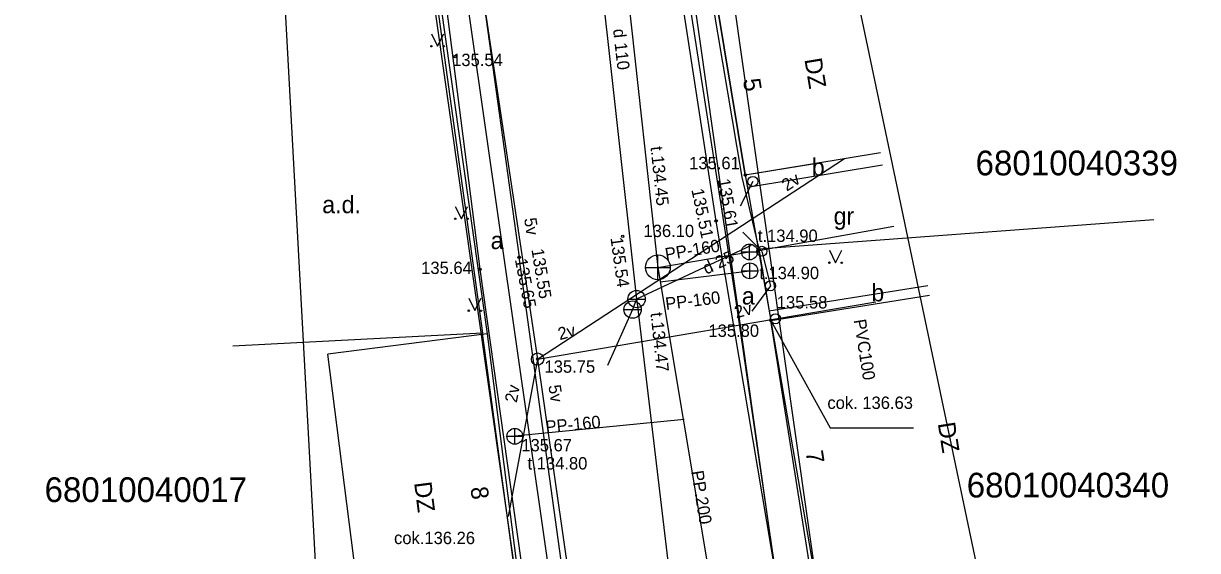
# Model space of a CAD drawing. Extents: x 728710 to 728960, y 272811 to 273475.
# Drawn here: x 728763.33 to 728810.77, y 273320.09 to 273341.41 of the extents above; entities that cross this region are included whole.
import ezdxf

# ---------------------------------------------------------------- set-up
doc = ezdxf.new("R2010")
doc.units = 0
for name, color, linetype in [('Level 15', 7, 'Continuous'), ('Level 17', 7, 'Continuous'), ('Level 21', 7, 'Continuous'), ('Level 23', 7, 'Continuous'), ('Level 25', 7, 'Continuous'), ('Level 28', 7, 'Continuous'), ('Level 29', 7, 'Continuous'), ('Level 3', 7, 'Continuous'), ('Level 35', 7, 'Continuous'), ('Level 39', 7, 'Continuous'), ('Level 4', 7, 'Continuous'), ('Level 41', 7, 'Continuous'), ('Level 42', 7, 'Continuous'), ('Level 43', 7, 'Continuous'), ('Level 48', 7, 'Continuous'), ('Level 50', 7, 'Continuous'), ('Level 53', 7, 'Continuous'), ('Level 55', 7, 'Continuous'), ('Level 56', 7, 'Continuous'), ('Level 57', 7, 'Continuous'), ('Level 58', 7, 'Continuous'), ('Level 59', 7, 'Continuous'), ('Level 60', 7, 'Continuous'), ('Level 62', 7, 'Continuous'), ('Level 9', 7, 'Continuous'), ('RAMI_UZMR_####_####_#', 7, 'Continuous'), ('ROBZ_ELEM_####_####_#', 7, 'Continuous'), ('ROBZ_KADS_####_TKST_#', 7, 'Continuous'), ('ROBZ_UZMR_####_####_#', 7, 'Continuous'), ('TERT_KOKR_####_####_#', 7, 'Continuous'), ('TERT_KONT_####_####_#', 7, 'Continuous')]:
    doc.layers.add(name, color=color, linetype=linetype)

msp = doc.modelspace()

# ---------------------------------------------------------------- linework, layer by layer
at = {"layer": 'Level 15'}
msp.add_circle((728784.106, 273327.834), 0.25, dxfattribs=at)
at = {"layer": 'Level 17'}
msp.add_line((728792.736, 273332.422), (728788.106, 273330.262), dxfattribs=at)
for points in [[(728784.072, 273366.484), (728788.106, 273330.262)], [(728788.106, 273330.262), (728787.947, 273329.838), (728786.937, 273327.58)], [(728788.106, 273330.262), (728788.125, 273330.089), (728790.41, 273310.945)]]:
    msp.add_lwpolyline(points, dxfattribs=at)
at = {"layer": 'Level 21'}
for p, q in [((728780.859, 273349.374), (728784.106, 273327.834)), ((728784.106, 273327.834), (728796.502, 273335.944)), ((728784.106, 273327.834), (728797.773, 273330.151)), ((728784.106, 273327.834), (728782.92, 273321.472)), ((728784.106, 273327.834), (728789.056, 273293.323))]:
    msp.add_line(p, q, dxfattribs=at)
at = {"layer": 'Level 23'}
for p, q in [((728785.477, 273363.156), (728788.967, 273331.545)), ((728788.967, 273331.545), (728792.668, 273332.168)), ((728788.967, 273331.545), (728795, 273295.478)), ((728789.065, 273330.958), (728792.684, 273331.404)), ((728790.024, 273325.392), (728783.185, 273324.713))]:
    msp.add_line(p, q, dxfattribs=at)
at = {"layer": 'Level 25'}
msp.add_lwpolyline([(728785.99, 273372.886), (728785.832, 273372.861), (728785.75, 273372.839), (728785.702, 273372.779), (728785.739, 273372.573), (728785.909, 273371.858), (728786.217, 273369.716), (728787.857, 273356.655), (728789.858, 273344.74), (728792.105, 273330.272), (728794.886, 273311.104), (728800.258, 273275.541), (728800.246, 273275.285), (728800.191, 273275.06), (728800.047, 273274.884), (728788.271, 273273.105), (728788.2, 273273.054), (728788.171, 273272.955), (728788.447, 273271.634)], dxfattribs=at)
at = {"layer": 'Level 28'}
msp.add_lwpolyline([(728793.169, 273332.187), (728793.514, 273330.801)], dxfattribs=at)
at = {"layer": 'Level 29'}
for p, q in [((728792.668, 273331.848), (728792.668, 273332.488)), ((728788.967, 273331.045), (728788.967, 273332.045)), ((728792.348, 273332.168), (728792.988, 273332.168)), ((728788.467, 273331.545), (728789.467, 273331.545)), ((728792.364, 273331.404), (728793.004, 273331.404)), ((728792.684, 273331.084), (728792.684, 273331.724)), ((728782.865, 273324.713), (728783.505, 273324.713)), ((728783.185, 273324.393), (728783.185, 273325.033))]:
    msp.add_line(p, q, dxfattribs=at)
for centre, radius in [((728792.668, 273332.168), 0.32), ((728788.967, 273331.545), 0.5), ((728792.684, 273331.404), 0.32), ((728783.185, 273324.713), 0.32)]:
    msp.add_circle(centre, radius, dxfattribs=at)
at = {"layer": 'Level 3'}
for p, q in [((728792.498, 273335.28), (728791.362, 273342.132)), ((728792.498, 273335.28), (728797.96, 273336.186)), ((728793.525, 273329.397), (728799.941, 273330.419)), ((728795.323, 273318.108), (728793.525, 273329.397)), ((728782.064, 273328.858), (728775.625, 273328.034)), ((728782.064, 273328.858), (728783.658, 273316.396)), ((728777.219, 273315.572), (728775.625, 273328.034))]:
    msp.add_line(p, q, dxfattribs=at)
msp.add_lwpolyline([(728794.003, 273342.57), (728791.362, 273342.132), (728792.498, 273335.28), (728795.229, 273335.733)], dxfattribs=at)
at = {"layer": 'Level 35'}
msp.add_lwpolyline([(728779.067, 273350.123), (728782.064, 273328.858)], dxfattribs=at)
at = {"layer": 'Level 39'}
for p, q in [((728787.755, 273330.262), (728788.458, 273330.262)), ((728788.105, 273330.262), (728788.105, 273330.263)), ((728787.595, 273329.838), (728788.298, 273329.838)), ((728787.946, 273329.838), (728787.946, 273329.839))]:
    msp.add_line(p, q, dxfattribs=at)
for centre in [(728788.106, 273330.262), (728787.947, 273329.838)]:
    msp.add_circle(centre, 0.351, dxfattribs=at)
at = {"layer": 'Level 4'}
for p, q in [((728792.584, 273334.788), (728798.042, 273335.692)), ((728792.498, 273335.28), (728793.525, 273329.397)), ((728794.133, 273316.778), (728791.32, 273333.416)), ((728793.456, 273329.791), (728799.878, 273330.814))]:
    msp.add_line(p, q, dxfattribs=at)
for points in [[(728779.361, 273361.614), (728781.472, 273345.559), (728783.362, 273331.954)], [(728791.32, 273333.416), (728787.038, 273361.283)], [(728778.618, 273353.363), (728780.022, 273345.193), (728781.779, 273331.467), (728784.112, 273314.817), (728786.279, 273299.247)], [(728793.032, 273332.221), (728798.502, 273333.21)], [(728787.818, 273299.7), (728783.362, 273331.954)]]:
    msp.add_lwpolyline(points, dxfattribs=at)
at = {"layer": 'Level 41'}
msp.add_lwpolyline([(728806.045, 273235.742), (728805.58, 273238.737), (728804.235, 273247.399), (728800.223, 273273.247), (728790.96, 273338.691), (728788.283, 273357.608), (728788.02, 273359.462)], dxfattribs=at)
at = {"layer": 'Level 42'}
msp.add_lwpolyline([(728778.361, 273363.303), (728780.185, 273349.821), (728787.396, 273299.393), (728788.824, 273288.687), (728789.966, 273279.612), (728789.68, 273278.991), (728788.986, 273278.539), (728787.225, 273277.322), (728786.051, 273275.933), (728786.004, 273273.362), (728785.463, 273272.543), (728783.043, 273271.508), (728782.567, 273270.973), (728782.471, 273270.304), (728783.044, 273269.874), (728783.9, 273270.126), (728785.092, 273270.261)], dxfattribs=at)
at = {"layer": 'Level 43'}
for p, q in [((728792.805, 273335.018), (728792.297, 273334.021)), ((728793.17, 273332.194), (728792.402, 273332.963)), ((728793.514, 273330.801), (728792.759, 273329.775))]:
    msp.add_line(p, q, dxfattribs=at)
for centre in [(728792.805, 273335.018), (728793.17, 273332.194), (728793.514, 273330.801), (728793.717, 273329.465)]:
    msp.add_circle(centre, 0.202, dxfattribs=at)
at = {"layer": 'Level 48'}
for centre in [(728780.772, 273340.067), (728792.498, 273335.28), (728791.32, 273333.416), (728787.545, 273332.801), (728783.362, 273331.954), (728781.779, 273331.467), (728793.525, 273329.397), (728784.106, 273327.834)]:
    msp.add_circle(centre, 0.05, dxfattribs=at)
at = {"layer": 'Level 9'}
msp.add_lwpolyline([(728793.525, 273329.397), (728795.934, 273325.057), (728799.291, 273325.057)], dxfattribs=at)
at = {"layer": 'RAMI_UZMR_####_####_#'}
msp.add_lwpolyline([(728810.773, 273260.978), (728802.611, 273315.901), (728795.796, 273348.362), (728794.274, 273357.438), (728805.771, 273362.009), (728805.234, 273373.998), (728803.936, 273379.727), (728791.234, 273379.578), (728787.734, 273403.429), (728803.558, 273404.599), (728803.908, 273418.239), (728787.419, 273421.679), (728754.475, 273424.404), (728743.982, 273420.563), (728745.23, 273392.888), (728745.879, 273378.489), (728747.149, 273361.103), (728773.116, 273356.557), (728775.22, 273317.659), (728767.872, 273315.668), (728768.286, 273308.258), (728775.846, 273306.093), (728776.746, 273299.712), (728774.767, 273288.109)], dxfattribs=at)
at = {"layer": 'ROBZ_ELEM_####_####_#'}
for points in [[(728809.55, 273219.213), (728789.366, 273361.101)], [(728797.679, 273217.456), (728777.701, 273357.893)]]:
    msp.add_lwpolyline(points, dxfattribs=at)
at = {"layer": 'ROBZ_UZMR_####_####_#'}
for p, q in [((728777.166, 273363.142), (728781.876, 273328.884)), ((728791.19, 273342.149), (728792.359, 273335.195)), ((728792.359, 273335.195), (728793.053, 273332.293)), ((728793.053, 273332.293), (728809.009, 273333.484)), ((728793.053, 273332.293), (728793.515, 273329.457)), ((728793.515, 273329.457), (728795.47, 273318.085)), ((728781.876, 273328.884), (728771.786, 273328.362)), ((728783.848, 273314.388), (728781.876, 273328.884))]:
    msp.add_line(p, q, dxfattribs=at)
at = {"layer": 'TERT_KONT_####_####_#'}
for p, q in [((728779.818, 273340.985), (728780.068, 273340.485)), ((728780.068, 273340.485), (728780.318, 273340.985)), ((728780.779, 273334.01), (728781.029, 273333.51)), ((728781.029, 273333.51), (728781.279, 273334.01)), ((728795.897, 273332.233), (728796.147, 273331.733)), ((728796.147, 273331.733), (728796.397, 273332.233)), ((728781.323, 273330.293), (728781.573, 273329.793)), ((728781.573, 273329.793), (728781.823, 273330.293))]:
    msp.add_line(p, q, dxfattribs=at)
for centre, radius in [((728779.818, 273340.485), 0.028), ((728780.318, 273340.485), 0.0263), ((728780.779, 273333.51), 0.028), ((728781.279, 273333.51), 0.0263), ((728795.897, 273331.733), 0.028), ((728796.397, 273331.733), 0.0263), ((728781.323, 273329.792), 0.028), ((728781.823, 273329.792), 0.0263)]:
    msp.add_circle(centre, radius, dxfattribs=at)

# ---------------------------------------------------------------- texts
at = {"layer": 'Level 50'}
for s, p in [('cok. 136.63', (728795.817, 273325.819)), ('cok.136.26', (728778.307, 273320.353))]:
    msp.add_text(s, height=0.5, dxfattribs=at).set_placement(p)
at = {"layer": 'Level 53'}
for s, rotation, p in [('2v', 33.195, (728794.177, 273334.602)), ('5v', 278.241, (728783.559, 273333.517)), ('2v', 15.234, (728792.136, 273329.479)), ('2v', 15.234, (728785.003, 273328.597)), ('2v', 79.436, (728783.265, 273326.048)), ('5v', 278.241, (728784.542, 273326.762))]:
    msp.add_text(s, height=0.5, rotation=rotation, dxfattribs=at).set_placement(p)
at = {"layer": 'Level 55'}
for s, rotation, p in [('d 110', 276.2873, (728787.154, 273341.167)), ('d 25', 25.0141, (728790.926, 273331.246))]:
    msp.add_text(s, height=0.5, rotation=rotation, dxfattribs=at).set_placement(p)
at = {"layer": 'Level 56'}
for s, p in [('136.10', (728788.387, 273332.77)), ('135.67', (728783.45, 273324.103))]:
    msp.add_text(s, height=0.5, dxfattribs=at).set_placement(p)
at = {"layer": 'Level 57'}
for s, p in [(' 135.54', (728780.468, 273339.684)), (' 135.61', (728790.046, 273335.513)), ('135.64', (728779.403, 273331.275)), ('135.58', (728793.771, 273329.881)), (' 135.80', (728790.824, 273328.734)), (' 135.75', (728784.201, 273327.282))]:
    msp.add_text(s, height=0.5, dxfattribs=at).set_placement(p)
for s, rotation, p in [('135.61', 279.8115, (728791.379, 273335.091)), ('135.51', 281.7646, (728790.318, 273334.682)), ('135.54', 277.8258, (728787.05, 273332.733)), ('135.55', 279.2592, (728783.855, 273332.264)), ('135.65', 280.8945, (728783.186, 273331.859))]:
    msp.add_text(s, height=0.5, rotation=rotation, dxfattribs=at).set_placement(p)
at = {"layer": 'Level 58'}
for s, p in [('b', (728795.187, 273335.252)), ('gr', (728796.068, 273333.272)), ('a', (728782.21, 273332.283)), ('b', (728797.592, 273330.169)), ('a', (728792.359, 273330.042))]:
    msp.add_text(s, height=0.7, dxfattribs=at).set_placement(p)
at = {"layer": 'Level 59'}
for rotation, p in [(279.413, (728794.886, 273339.957)), (279.049, (728800.274, 273325.232)), (277.289, (728779.115, 273322.834))]:
    msp.add_text('DZ', height=0.7, rotation=rotation, dxfattribs=at).set_placement(p)
at = {"layer": 'Level 60'}
for s, rotation, p in [('t.134.45', 276.0007, (728788.668, 273336.415)), ('PP-160', 9.5586, (728789.3, 273331.82)), ('PP-160', 7.0289, (728789.3, 273329.822)), ('t.134.47', 276.0007, (728788.668, 273329.7)), ('PVC100', 279.049, (728796.876, 273329.411)), ('PP-160', 5.662, (728784.455, 273324.839)), ('PP.200', 279.249, (728790.31, 273323.289))]:
    msp.add_text(s, height=0.5, rotation=rotation, dxfattribs=at).set_placement(p)
for s, p in [('t.134.90', (728793.008, 273332.573)), ('t.134.90', (728793.064, 273331.068)), ('t.134.80', (728783.7, 273323.37))]:
    msp.add_text(s, height=0.5, dxfattribs=at).set_placement(p)
at = {"layer": 'Level 62'}
for s, rotation, p in [('5', 279.413, (728792.4, 273339.132)), ('7', 279.049, (728794.934, 273324.083)), ('8', 277.289, (728781.392, 273322.636))]:
    msp.add_text(s, height=0.7, rotation=rotation, dxfattribs=at).set_placement(p)
at = {"layer": 'ROBZ_KADS_####_TKST_#'}
for s, p in [('68010040339', (728801.804, 273335.266)), ('68010040340', (728801.447, 273322.238)), ('68010040017', (728764.184, 273322.053))]:
    msp.add_text(s, height=1, dxfattribs=at).set_placement(p)
at = {"layer": 'TERT_KOKR_####_####_#'}
msp.add_text('a.d.', height=0.7, dxfattribs=at).set_placement((728775.405, 273333.735))

doc.saveas('drawing.dxf')
